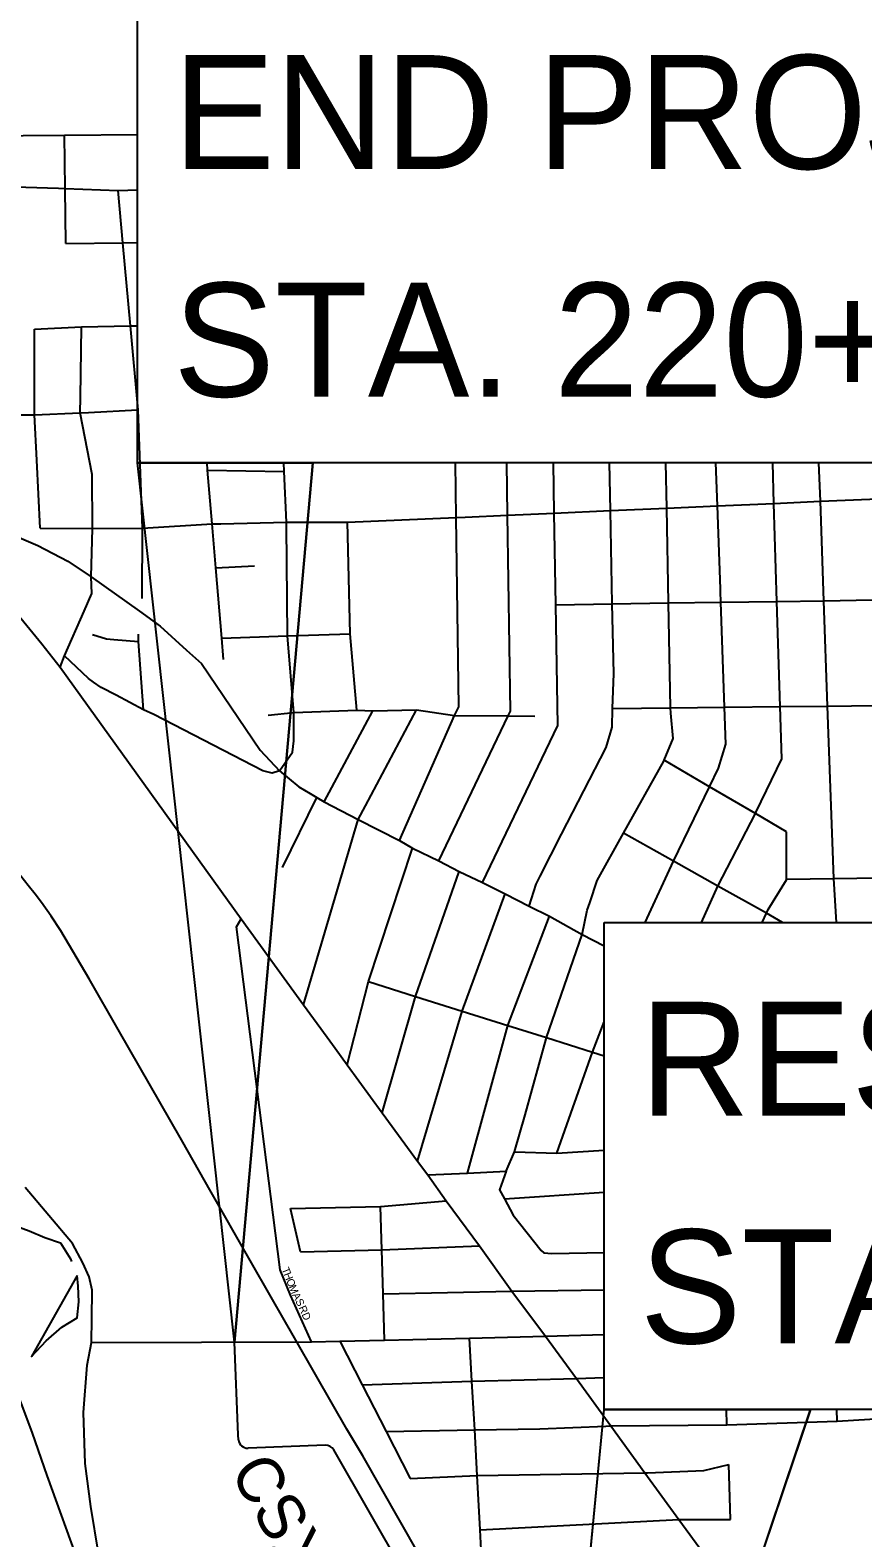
# Model space of a CAD drawing. Extents: x -37878.7 to -37844.7, y -19791.4 to -19769.4.
# Drawn here: x -37874.951 to -37873.927, y -19773.183 to -19771.329 of the extents above; entities that cross this region are included whole.
import ezdxf

# ---------------------------------------------------------------- set-up
doc = ezdxf.new("R2010")
doc.units = 0
for name, color, linetype in [('Default', 7, 'Continuous'), ('GM_X_City_Street', 7, 'Continuous'), ('GM_X_County_Road', 7, 'Continuous'), ('GM_X_Minor_River', 7, 'Continuous'), ('GM_X_Rail_Line', 7, 'Continuous'), ('GM_X_Rail_Line_Text', 7, 'Continuous'), ('GM_X_State_Route', 7, 'Continuous'), ('GM_X_US_Route', 7, 'Continuous'), ('SH_Data', 7, 'Continuous'), ('TX_P_1', 7, 'Continuous')]:
    doc.layers.add(name, color=color, linetype=linetype)

msp = doc.modelspace()

# ---------------------------------------------------------------- linework, layer by layer
at = {"layer": 'Default'}
msp.add_lwpolyline([(-37874.6048, -19772.9418), (-37874.6305, -19772.8845), (-37874.6434, -19772.8531)], dxfattribs=at)
at = {"layer": 'GM_X_City_Street'}
for points in [[(-37875.108, -19771.4473), (-37875.0949, -19771.4584), (-37875.0019, -19771.459), (-37874.9591, -19771.4586), (-37874.9086, -19771.4582), (-37874.8187, -19771.4574)], [(-37874.907, -19771.5912), (-37874.9078, -19771.5237), (-37874.9086, -19771.4582)], [(-37874.9965, -19771.5206), (-37874.9159, -19771.5234), (-37874.9158, -19771.5234)], [(-37874.9158, -19771.5234), (-37874.9078, -19771.5237), (-37874.8423, -19771.526), (-37874.8187, -19771.5254)], [(-37874.8181, -19771.796), (-37874.8274, -19771.6926), (-37874.8366, -19771.5904), (-37874.8423, -19771.526)], [(-37874.907, -19771.5912), (-37874.8366, -19771.5904), (-37874.8187, -19771.5902)], [(-37874.9455, -19771.6967), (-37874.8876, -19771.6937), (-37874.8274, -19771.6926), (-37874.8187, -19771.6924)], [(-37874.9453, -19771.802), (-37874.9455, -19771.6967)], [(-37874.889, -19771.7802), (-37874.8876, -19771.6937)], [(-37874.8893, -19771.7994), (-37874.889, -19771.7802), (-37874.889, -19771.7802)], [(-37874.879, -19771.7989), (-37874.8187, -19771.796)], [(-37874.8128, -19772.0278), (-37874.8125, -19771.9412), (-37874.8181, -19771.796)], [(-37875.0715, -19771.8021), (-37875.0715, -19771.8021), (-37874.9453, -19771.802), (-37874.8893, -19771.7994), (-37874.879, -19771.7989)], [(-37874.9426, -19771.8578), (-37874.9453, -19771.802)], [(-37874.914, -19772.1122), (-37874.9084, -19772.0985), (-37874.8845, -19772.0435), (-37874.8747, -19772.0216), (-37874.8756, -19772.0013), (-37874.8741, -19771.9418), (-37874.8744, -19771.8753), (-37874.8893, -19771.7994)], [(-37874.9385, -19771.9414), (-37874.9426, -19771.8578), (-37874.9426, -19771.8578)], [(-37874.7129, -19772.1028), (-37874.7151, -19772.0766), (-37874.7224, -19771.99), (-37874.7269, -19771.9361), (-37874.7325, -19771.8698), (-37874.7332, -19771.8611)], [(-37874.7325, -19771.8698), (-37874.6383, -19771.8717)], [(-37874.6441, -19772.2399), (-37874.6282, -19772.2167), (-37874.6263, -19772.203), (-37874.6266, -19772.168), (-37874.6343, -19772.0739), (-37874.6354, -19771.9388), (-37874.6356, -19771.9339), (-37874.6383, -19771.8717), (-37874.6388, -19771.8611)], [(-37874.4966, -19772.3254), (-37874.429, -19772.1718), (-37874.4235, -19772.1611), (-37874.4268, -19771.9281), (-37874.4277, -19771.8611)], [(-37874.4482, -19772.3502), (-37874.363, -19772.1722), (-37874.36, -19772.1663), (-37874.3637, -19771.9253), (-37874.3647, -19771.8611)], [(-37874.3945, -19772.3769), (-37874.3017, -19772.1838), (-37874.3043, -19772.0354), (-37874.3062, -19771.9227), (-37874.3073, -19771.8611)], [(-37874.3235, -19772.3693), (-37874.2974, -19772.3177), (-37874.2423, -19772.2111), (-37874.2352, -19772.1862), (-37874.2345, -19772.1629), (-37874.2332, -19772.12), (-37874.2349, -19772.0343), (-37874.2373, -19771.9197), (-37874.2385, -19771.8611)], [(-37874.2627, -19772.402), (-37874.2535, -19772.3744), (-37874.2211, -19772.3165), (-37874.1715, -19772.2278), (-37874.1711, -19772.2267), (-37874.16, -19772.2), (-37874.1631, -19772.169), (-37874.1632, -19772.1621), (-37874.1657, -19772.0333), (-37874.1679, -19771.9166), (-37874.1689, -19771.8611)], [(-37874.1253, -19772.4261), (-37874.105, -19772.3815), (-37874.059, -19772.2922), (-37874.058, -19772.2902), (-37874.0263, -19772.2248), (-37874.0283, -19772.1606), (-37874.0324, -19772.0313), (-37874.0362, -19771.9108), (-37874.0377, -19771.8611)], [(-37874.102, -19772.0161), (-37874.1056, -19771.9138), (-37874.1075, -19771.8611)], [(-37873.9591, -19772.4261), (-37873.9627, -19772.3721), (-37873.9702, -19772.16), (-37873.9748, -19772.0305), (-37873.9791, -19771.9083), (-37873.9808, -19771.8611)], [(-37874.416, -19771.9276), (-37874.4157, -19771.9276), (-37874.3637, -19771.9253), (-37874.3062, -19771.9227), (-37874.2373, -19771.9197), (-37874.1679, -19771.9166), (-37874.1056, -19771.9138), (-37874.0362, -19771.9108), (-37873.9791, -19771.9083), (-37873.9181, -19771.9055), (-37873.9151, -19771.9054), (-37873.8609, -19771.9056), (-37873.8173, -19771.904), (-37873.7151, -19771.9143), (-37873.6249, -19771.8966), (-37873.5479, -19771.8952), (-37873.4678, -19771.8936)], [(-37874.9385, -19771.9414), (-37874.8741, -19771.9418), (-37874.8125, -19771.9412), (-37874.7269, -19771.9361), (-37874.7164, -19771.9359)], [(-37874.7164, -19771.9359), (-37874.7164, -19771.9359), (-37874.6356, -19771.9339), (-37874.5603, -19771.934), (-37874.4268, -19771.9281), (-37874.416, -19771.9276)], [(-37874.549, -19772.1652), (-37874.5571, -19772.0713), (-37874.5603, -19771.934)], [(-37874.7224, -19771.99), (-37874.6747, -19771.9878)], [(-37874.1943, -19772.4261), (-37874.1598, -19772.3508), (-37874.1154, -19772.2593), (-37874.1044, -19772.2366), (-37874.0953, -19772.207), (-37874.0969, -19772.1614), (-37874.1014, -19772.0323), (-37874.1019, -19772.0193), (-37874.102, -19772.0161)], [(-37874.3043, -19772.0354), (-37874.2349, -19772.0343), (-37874.1657, -19772.0333), (-37874.1014, -19772.0323), (-37874.0324, -19772.0313), (-37873.9748, -19772.0305), (-37873.9148, -19772.0296)], [(-37874.874, -19772.0722), (-37874.8568, -19772.0776), (-37874.848, -19772.0784), (-37874.8176, -19772.0806)], [(-37874.8114, -19772.1645), (-37874.8176, -19772.0806), (-37874.8175, -19772.0715)], [(-37874.7151, -19772.0766), (-37874.6343, -19772.0739), (-37874.5571, -19772.0713)], [(-37874.6441, -19772.2399), (-37874.653, -19772.2425), (-37874.6648, -19772.2399), (-37874.7985, -19772.1703), (-37874.8114, -19772.1645), (-37874.845, -19772.1467), (-37874.8633, -19772.1372), (-37874.8727, -19772.1308), (-37874.8789, -19772.1262), (-37874.9084, -19772.0985)], [(-37874.6579, -19772.1713), (-37874.6266, -19772.168), (-37874.549, -19772.1652), (-37874.5292, -19772.1658), (-37874.4758, -19772.1649), (-37874.429, -19772.1718), (-37874.363, -19772.1722), (-37874.3302, -19772.1723)], [(-37874.5891, -19772.2778), (-37874.5292, -19772.1658)], [(-37874.5385, -19772.2827), (-37874.4758, -19772.1649)], [(-37874.2345, -19772.1629), (-37874.1632, -19772.1621), (-37874.0969, -19772.1614), (-37874.0283, -19772.1606), (-37873.9702, -19772.16), (-37873.9114, -19772.1593)], [(-37874.0207, -19772.3146), (-37874.059, -19772.2922), (-37874.1154, -19772.2593), (-37874.1711, -19772.2267)], [(-37874.6406, -19772.3586), (-37874.5984, -19772.2723)], [(-37874.6148, -19772.5274), (-37874.5475, -19772.2996), (-37874.5385, -19772.2827)], [(-37874.0508, -19772.4261), (-37874.0455, -19772.4149), (-37874.0432, -19772.4104), (-37874.0207, -19772.3739), (-37874.0207, -19772.3731), (-37874.0207, -19772.3146)], [(-37874.0255, -19772.4261), (-37874.0455, -19772.4149), (-37874.105, -19772.3815), (-37874.1598, -19772.3508), (-37874.2211, -19772.3165)], [(-37874.5609, -19772.6013), (-37874.5347, -19772.4989), (-37874.4807, -19772.3349)], [(-37874.518, -19772.6601), (-37874.4768, -19772.5172), (-37874.4231, -19772.3633)], [(-37874.3371, -19772.4061), (-37874.3284, -19772.379), (-37874.3235, -19772.3693)], [(-37874.0207, -19772.3731), (-37873.9627, -19772.3721), (-37873.9058, -19772.3712), (-37873.7967, -19772.3693), (-37873.7006, -19772.3589), (-37873.6122, -19772.3653), (-37873.5284, -19772.3638), (-37873.4553, -19772.363), (-37873.4064, -19772.3625)], [(-37874.4743, -19772.7196), (-37874.4195, -19772.5352), (-37874.3668, -19772.3909)], [(-37874.3654, -19772.732), (-37874.355, -19772.7081), (-37874.3419, -19772.6627), (-37874.3163, -19772.5694), (-37874.3158, -19772.5678), (-37874.2718, -19772.4408), (-37874.2657, -19772.4111), (-37874.2627, -19772.402)], [(-37874.6434, -19772.8531), (-37874.6971, -19772.4316), (-37874.6913, -19772.4218)], [(-37874.4128, -19772.7343), (-37874.3633, -19772.5529), (-37874.3123, -19772.4183)], [(-37874.5347, -19772.4989), (-37874.4768, -19772.5172), (-37874.4195, -19772.5352), (-37874.3633, -19772.5529), (-37874.3158, -19772.5678), (-37874.2594, -19772.5856), (-37874.245, -19772.5901)], [(-37874.303, -19772.7098), (-37874.2594, -19772.5856), (-37874.245, -19772.5485)], [(-37874.355, -19772.7081), (-37874.303, -19772.7098), (-37874.245, -19772.7062)], [(-37874.4618, -19772.7366), (-37874.4128, -19772.7343), (-37874.3654, -19772.732)], [(-37874.3654, -19772.732), (-37874.3734, -19772.755), (-37874.3676, -19772.766), (-37874.357, -19772.7862), (-37874.3225, -19772.8296), (-37874.3189, -19772.8326), (-37874.3094, -19772.8334), (-37874.245, -19772.8319)], [(-37874.3676, -19772.766), (-37874.245, -19772.758)], [(-37874.6304, -19772.7778), (-37874.5198, -19772.7754), (-37874.439, -19772.7683)], [(-37874.6181, -19772.8312), (-37874.6304, -19772.7778)], [(-37874.515, -19772.9397), (-37874.5167, -19772.8827), (-37874.5182, -19772.8287), (-37874.5198, -19772.7754)], [(-37874.6181, -19772.8312), (-37874.5182, -19772.8287), (-37874.3983, -19772.8237)], [(-37874.5167, -19772.8827), (-37874.3584, -19772.8795), (-37874.245, -19772.8777)], [(-37874.8752, -19772.9426), (-37874.6048, -19772.9418), (-37874.57, -19772.941), (-37874.515, -19772.9397), (-37874.4105, -19772.9373), (-37874.3169, -19772.9348), (-37874.245, -19772.933)], [(-37874.57, -19772.941), (-37874.5425, -19772.9946), (-37874.5131, -19773.0522), (-37874.4836, -19773.1097)], [(-37874.2653, -19773.2874), (-37874.2633, -19773.3097), (-37874.266, -19773.3288), (-37874.2727, -19773.3404), (-37874.2814, -19773.3427), (-37874.3029, -19773.3439), (-37874.3132, -19773.3416), (-37874.3214, -19773.3374), (-37874.3365, -19773.3193), (-37874.3856, -19773.2233), (-37874.3906, -19773.2132), (-37874.3961, -19773.1975), (-37874.3974, -19773.1728), (-37874.401, -19773.1061), (-37874.4041, -19773.05), (-37874.4048, -19773.0368), (-37874.4075, -19772.99), (-37874.4105, -19772.9373)], [(-37874.5425, -19772.9946), (-37874.4075, -19772.99), (-37874.2791, -19772.9871), (-37874.245, -19772.9857)], [(-37874.243, -19773.0455), (-37874.2367, -19773.0452), (-37874.0939, -19773.0438), (-37873.9584, -19773.0393), (-37873.7706, -19773.0279)], [(-37874.0939, -19773.0438), (-37874.0946, -19773.0251)], [(-37873.9584, -19773.0393), (-37873.9587, -19773.0251)], [(-37874.5131, -19773.0522), (-37874.4041, -19773.05), (-37874.3239, -19773.0488), (-37874.243, -19773.0455)], [(-37874.1915, -19773.1028), (-37874.1224, -19773.1002), (-37874.0917, -19773.0926)], [(-37874.0895, -19773.1603), (-37874.0917, -19773.0926)], [(-37874.4836, -19773.1097), (-37874.401, -19773.1061), (-37874.1948, -19773.1029), (-37874.1915, -19773.1028)], [(-37874.3974, -19773.1728), (-37874.153, -19773.1601), (-37874.0895, -19773.1603)]]:
    msp.add_lwpolyline(points, dxfattribs=at)
at = {"layer": 'GM_X_County_Road'}
for points in [[(-37874.8749, -19772.913), (-37874.8745, -19772.8782), (-37874.8783, -19772.8619), (-37874.8861, -19772.8448), (-37874.8985, -19772.8208), (-37874.9569, -19772.7519)], [(-37874.4179, -19774.0787), (-37874.4674, -19774.0334), (-37874.534, -19773.9915), (-37874.5577, -19773.9646), (-37874.5722, -19773.9411), (-37874.581, -19773.9263), (-37874.589, -19773.9104), (-37874.6017, -19773.8797), (-37874.6594, -19773.7706), (-37874.7103, -19773.6739), (-37874.7387, -19773.6023), (-37874.7648, -19773.5257), (-37874.8527, -19773.2607), (-37874.8667, -19773.2017), (-37874.876, -19773.1443), (-37874.883, -19773.0915), (-37874.8853, -19773.0287), (-37874.8807, -19772.9705), (-37874.8752, -19772.9426), (-37874.8749, -19772.913)]]:
    msp.add_lwpolyline(points, dxfattribs=at)
at = {"layer": 'GM_X_Minor_River'}
for points in [[(-37874.979, -19772.9353), (-37875.0396, -19772.7738), (-37875.0626, -19772.7059), (-37875.0434, -19772.7009), (-37875.0445, -19772.682), (-37875.0637, -19772.6733), (-37875.066, -19772.6536), (-37875.0468, -19772.6642), (-37875.0275, -19772.6831), (-37875.0206, -19772.7023), (-37875.0278, -19772.7226), (-37875.0122, -19772.7416), (-37874.9974, -19772.7614), (-37874.9906, -19772.7807), (-37874.9709, -19772.7984), (-37874.9518, -19772.8052), (-37874.9327, -19772.8136), (-37874.9132, -19772.82), (-37874.9011, -19772.8398), (-37874.8999, -19772.8432)], [(-37874.8931, -19772.8602), (-37874.949, -19772.9597), (-37874.9312, -19772.9407), (-37874.9118, -19772.924), (-37874.8927, -19772.9122), (-37874.8909, -19772.8928), (-37874.8917, -19772.8734), (-37874.8931, -19772.8602)]]:
    msp.add_lwpolyline(points, dxfattribs=at)
at = {"layer": 'GM_X_Rail_Line'}
for points in [[(-37874.6273, -19772.9339), (-37874.6529, -19772.8899), (-37874.6818, -19772.8388), (-37874.7281, -19772.7578), (-37874.7648, -19772.6936), (-37874.8424, -19772.5579), (-37874.8781, -19772.4953), (-37874.9128, -19772.4366), (-37874.925, -19772.4185), (-37874.9369, -19772.4018), (-37874.9446, -19772.3914), (-37874.9531, -19772.3808), (-37874.9621, -19772.3691), (-37874.9709, -19772.3587), (-37874.9861, -19772.3408), (-37875.0118, -19772.315), (-37875.029, -19772.2981), (-37875.0428, -19772.2854), (-37875.0592, -19772.272), (-37875.0718, -19772.2616), (-37875.082, -19772.2538), (-37875.1028, -19772.2385)], [(-37874.45, -19773.2432), (-37874.5416, -19773.082), (-37874.5614, -19773.0492), (-37874.5983, -19772.9847), (-37874.6273, -19772.9339)], [(-37874.8892, -19773.2183), (-37874.9297, -19773.106), (-37874.948, -19773.054), (-37874.9702, -19772.9937)]]:
    msp.add_lwpolyline(points, dxfattribs=at)
at = {"layer": 'GM_X_State_Route'}
for points in [[(-37875.0709, -19771.9471), (-37875.0611, -19771.9605), (-37874.9872, -19772.0295), (-37874.962, -19772.052), (-37874.9365, -19772.0837), (-37874.914, -19772.1122), (-37874.6913, -19772.4218), (-37874.6148, -19772.5274), (-37874.5854, -19772.5673), (-37874.5756, -19772.5808)], [(-37874.5756, -19772.5808), (-37874.5609, -19772.6013), (-37874.518, -19772.6601), (-37874.4743, -19772.7196), (-37874.4618, -19772.7366), (-37874.439, -19772.7683), (-37874.3983, -19772.8237), (-37874.3584, -19772.8795), (-37874.3169, -19772.9348), (-37874.2791, -19772.9871), (-37874.2367, -19773.0452), (-37874.1948, -19773.1029), (-37874.153, -19773.1601), (-37874.0667, -19773.2784), (-37874.0313, -19773.3276), (-37874.0229, -19773.3382), (-37874.0054, -19773.3627)]]:
    msp.add_lwpolyline(points, dxfattribs=at)
at = {"layer": 'GM_X_US_Route'}
for points in [[(-37875.0709, -19771.9471), (-37875.0088, -19771.947), (-37874.9874, -19771.9477), (-37874.9643, -19771.9529), (-37874.9412, -19771.9627), (-37874.9042, -19771.9819), (-37874.8756, -19772.0013), (-37874.8161, -19772.0435), (-37874.7907, -19772.062), (-37874.7584, -19772.0912), (-37874.7399, -19772.1076), (-37874.668, -19772.2142), (-37874.6441, -19772.2399)], [(-37874.6441, -19772.2399), (-37874.6203, -19772.2595), (-37874.6065, -19772.2676)], [(-37874.6065, -19772.2676), (-37874.5984, -19772.2723), (-37874.5891, -19772.2778), (-37874.5475, -19772.2996), (-37874.4966, -19772.3254), (-37874.4807, -19772.3349), (-37874.4482, -19772.3502), (-37874.4231, -19772.3633), (-37874.3945, -19772.3769), (-37874.3668, -19772.3909), (-37874.3371, -19772.4061), (-37874.3123, -19772.4183), (-37874.2718, -19772.4408), (-37874.245, -19772.455)]]:
    msp.add_lwpolyline(points, dxfattribs=at)
at = {"layer": 'SH_Data'}
for p, q in [((-37874.6951, -19773.0562), (-37874.6995, -19772.9421)), ((-37874.6945, -19773.0624), (-37874.6951, -19773.0562)), ((-37874.5876, -19773.069), (-37874.6827, -19773.0725)), ((-37874.1345, -19773.8481), (-37874.5773, -19773.0747))]:
    msp.add_line(p, q, dxfattribs=at)
for centre, start, end in [((-37874.6832, -19773.0612), 186.0923, 272.1417), ((-37874.5872, -19773.0803), 29.7955, 92.1417)]:
    msp.add_arc(centre, 0.0114, start, end, dxfattribs=at)
at = {"layer": 'TX_P_1'}
for p, q in [((-37874.8187, -19771.8611), (-37874.8187, -19771.262)), ((-37873.0606, -19771.8611), (-37874.8187, -19771.8611)), ((-37874.6995, -19772.9421), (-37874.8187, -19771.8611)), ((-37874.6995, -19772.9421), (-37874.6031, -19771.8611)), ((-37874.245, -19772.4261), (-37872.2662, -19772.4261)), ((-37874.245, -19773.0251), (-37874.245, -19772.4261)), ((-37874.3457, -19774.0758), (-37874.245, -19773.0251)), ((-37874.3457, -19774.0758), (-37873.9912, -19773.0251)), ((-37872.2662, -19773.0251), (-37874.245, -19773.0251))]:
    msp.add_line(p, q, dxfattribs=at)
for points in [[(-37874.6995, -19772.9421), (-37874.8187, -19771.8611), (-37874.6031, -19771.8611)], [(-37874.3457, -19774.0758), (-37874.245, -19773.0251), (-37873.9912, -19773.0251)]]:
    msp.add_lwpolyline(points, close=True, dxfattribs=at)

# ---------------------------------------------------------------- texts
at = {"layer": 'Default'}
for s, rotation, p in [('T', 291.5985, (-37874.6417, -19772.8524)), ('H', 291.5985, (-37874.6392, -19772.8586)), ('O', 291.5985, (-37874.6361, -19772.8663)), ('M', 292.2208, (-37874.633, -19772.8742)), ('A', 296.8648, (-37874.6289, -19772.8842)), ('S', 297.8964, (-37874.625, -19772.8918)), ('RD', 293.9614, (-37874.6209, -19772.8998))]:
    msp.add_text(s, height=0.00947, rotation=rotation, dxfattribs=at).set_placement(p)
at = {"layer": 'GM_X_Rail_Line_Text'}
msp.add_text('CSX Transportation, Inc.', height=0.056629, rotation=299.7135, dxfattribs=at).set_placement((-37874.706, -19773.1008))
at = {"layer": 'TX_P_1'}
for s, p in [('END PROJECT', (-37874.7747, -19771.4996)), ('STA. 220+85.73', (-37874.7747, -19771.7796)), ('RESUME PROJECT', (-37874.201, -19772.6637)), ('STA. 144+48.49', (-37874.201, -19772.9437))]:
    msp.add_text(s, height=0.14, rotation=360, dxfattribs=at).set_placement(p)

doc.saveas('drawing.dxf')
